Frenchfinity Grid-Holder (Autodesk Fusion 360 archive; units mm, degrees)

design "Grid-Holder" references "Base"
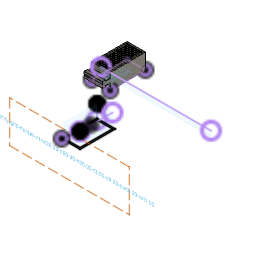
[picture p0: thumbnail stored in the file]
parameter "width" = 26
parameter "depth" = 50
parameter "height" = 20
parameter "outer_wall_thickness" = 2
parameter "inner_wall_thickness" = 1
sketch "Sketch1" plane through (0, 0, 0) normal (0, 0, 1) x axis (1, 0, 0)
  line L1 (26, 0) -> (0, 0)
  line L2 (0, 50) -> (0, 0)
  line L3 (26, 50) -> (0, 50)
  line L4 (26, 0) -> (26, 50)
  line L5 (24, 2) -> (2, 2)
  line L6 (24, 2) -> (24, 48)
  line L7 (24, 48) -> (2, 48)
  line L8 (2, 48) -> (2, 2)
  point P1 (0, 0)
  point P2 (0, 0)
  point P4 (0, 0)
  point P3 (26, 0)
  point P5 (0, 50)
  coincident P1 P2
  horizontal L1
  coincident P1 P4
  perpendicular L1 L2
  perpendicular L2 L3
  equal L1 L3
  dimension "d7" distance P2 P3 = 26 (= "width")
  dimension "d8" distance P4 P5 = 50 (= "depth")
  dimension "d11" = 2 (= "outer_wall_thickness")
extrude "Extrude1" new body sketch "Sketch1" against normal blind 2 (magnitude of "outer_wall_thickness * -1") bodies "Case"
extrude "Extrude2" add sketch "Sketch1" along normal blind 20 (= "height")
sketch "Sketch2" plane through (0, 0, 0) normal (0, 0, 1) x axis (1, 0, 0)
  line L1 (24, 48) -> (24, 2)
  line L2 (2, 48) -> (24, 48)
  line L3 (2, 2) -> (2, 48)
  line L4 (24, 2) -> (2, 2)
  line L5 (24, 25) -> (2, 25)
  line L6 (2, 25.5) -> (24, 25.5)
  line L7 (2, 24.5) -> (2, 25.5)
  line L8 (24, 24.5) -> (2, 24.5)
  line L9 (24, 25.5) -> (24, 24.5)
  line L10 (2, 24.5) -> (24, 25.5)
  line L11 (24, 24.5) -> (2, 25.5)
  point P6 (2, 25)
  point P7 (24, 25)
  point P12 (13, 25)
  point P9 (2, 25.5)
  point P10 (2, 24.5)
  point P11 (24, 24.5)
  midpoint L3 P6
  midpoint L1 P7
  horizontal L6
  perpendicular L6 L7
  parallel L6 L8
  parallel L7 L9
  coincident L10 P12
  coincident L11 P12
  midpoint L5 P12
  dimension "d16" distance P9 P10 = 1 (= "inner_wall_thickness")
  dimension "d23" distance P10 P11 = 22 (= "width - outer_wall_thickness - outer_wall_thickness")
extrude "Extrude3" new body sketch "Sketch2" profile of L1 L3 L6 L8 along normal blind 20 (= "height") bodies "Row-Divider"
sketch "Sketch3" plane through (0, 0, 0) normal (0, 0, 1) x axis (1, 0, 0)
  line L1 (24, 2) -> (2, 2)
  line L2 (24, 48) -> (2, 48)
  line L3 (13, 48) -> (13, 2)
  line L4 (13.5, 48) -> (12.5, 48)
  line L5 (13.5, 2) -> (13.5, 48)
  line L6 (12.5, 2) -> (13.5, 2)
  line L7 (12.5, 48) -> (12.5, 2)
  line L8 (13.5, 2) -> (12.5, 48)
  line L9 (12.5, 2) -> (13.5, 48)
  point P6 (13, 2)
  point P7 (13, 48)
  point P12 (13, 25)
  point P9 (13.5, 48)
  point P10 (13.5, 2)
  point P8 (12.5, 48)
  midpoint L1 P6
  midpoint L2 P7
  horizontal L4
  perpendicular L4 L5
  parallel L4 L6
  parallel L5 L7
  coincident L8 P12
  coincident L9 P12
  midpoint L3 P12
  dimension "d24" distance P9 P10 = 46 (= "depth - outer_wall_thickness - outer_wall_thickness")
  dimension "d25" distance P8 P9 = 1 (= "inner_wall_thickness")
extrude "Extrude4" new body sketch "Sketch3" profile of L4 L5 L6 L7 along normal blind 20 (= "height") bodies "Column-Divider"
sketch "Sketch5" plane through (0, 48, 0) normal (0, -1, 0) x axis (1, 0, 0)
  line L1 (24, 0) -> (2, 0)
  line L2 (24, 20) -> (24, 0)
  line L3 (2, 20) -> (24, 20)
  line L4 (2, 0) -> (2, 20)
  line L5 (2, 20) -> (2, 0)
  line L6 (4.4568, 20) -> (2, 20)
  point P7 (2, 20)
  point P8 (2, 20)
  point P9 (4.4568, 20)
  coincident P7 P8
  perpendicular L5 L6
  dimension "d32" distance P8 P9 = 2.4568 (= "column_width_calculated")
move "Move1"
rectangular_pattern "R-Pattern3" countU 8 (= "columns - 1") uSpaceDistance -2.4568 (= "column_width_calculated * -1") vSpaceDistance 0 bodies "Column-Divider (1)", "Column-Divider (2)", "Column-Divider (3)", "Column-Divider (4)", "Column-Divider (5)", "Column-Divider (6)", "Column-Divider (7)"
sketch "Sketch6" plane through (2, 0, 0) normal (1, 0, 0) x axis (0, 1, 0)
  line L1 (48, 0) -> (2, 0)
  line L2 (48, 20) -> (48, 0)
  line L3 (2, 20) -> (48, 20)
  line L4 (2, 0) -> (2, 20)
  line L5 (17.4444, 20) -> (2, 20)
  line L6 (2, 20) -> (48, 20)
  point P6 (2, 20)
  point P7 (2, 20)
  point P8 (17.4444, 20)
  coincident P6 P7
  parallel L5 L6
  dimension "d39" distance P7 P8 = 15.4444 (= "row_width_calculated")
move "Move2"
rectangular_pattern "R-Pattern4" countU 2 (= "rows - 1") uSpaceDistance 15.4444 (= "row_width_calculated") vSpaceDistance 0 bodies "Row-Divider (1)"
component_insert "Component Insert"
sketch "Sketch7" plane through (0, 55.6118, 0) normal (0, 1, 0) x axis (-1, 0, 0)
  line L1 (0, 52.6059) -> (-156, 52.6059)
  line L2 (0, 60) -> (0, 52.6059)
  line L3 (-156, 60) -> (0, 60)
  line L4 (-156, 52.6059) -> (-156, 60)
  line L5 (-156, 60) -> (0, 60)
combine "Combine1" bodies "Column-Divider (6)", "Column-Divider (3)", "Column-Divider (2)", "Row-Divider (1)", "Column-Divider (4)", "Column-Divider (5)", "Column-Divider (7)", "Column-Divider (1)"
move "Move3"
extrude "Extrude5" add of existing geometry to an object
extrude "Extrude6" add of existing geometry to an object
sketch "Text" plane through (0, 0, 38) normal (0, 0, -1) x axis (1, 0, 0)
  dimension "d48" = 3
extrude "Extrude7" cut sketch "Text" against normal blind 2
sketch "File name" plane through (0, 0, 0) normal (0, 1, 0) x axis (1, 0, 0)
  dimension "d51" = 5
named bodies: "Case", "Row-Divider", "Column-Divider", "Column-Divider (1)", "Column-Divider (2)", "Column-Divider (3)", "Column-Divider (4)", "Column-Divider (5)", "Column-Divider (6)", "Column-Divider (7)", "Row-Divider (1)"

design "Base"
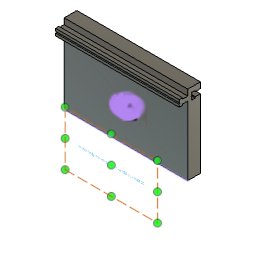
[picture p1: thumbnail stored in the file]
parameter "wall_anchor_height" = 60
parameter "wall_anchor_width" = 20
parameter "wall_anchor_angle" = 45
parameter "width_per_slot" = 40
parameter "slot_inner_width" = 8.5
parameter "slot_inner_height" = 4.5
parameter "slot_outer_width" = 5.6
parameter "slot_outer_height" = 6.5
parameter "slot_dept" = 15
parameter "print_tolerance" = 0.12
parameter "base_plate_thickness" = 16
parameter "base_plate_slot_height" = 50
parameter "wall_anchor_angle_rounded_border" = 1.5
parameter "base_plate_screw_hole_diameter" = 4
parameter "base_plate_screw_head_diameter" = 8
parameter "base_plate_screw_head_height" = 4
parameter "base_plate_screw_hole_side_distance" = 7
parameter "slot_screw_head_width" = 4.42 (= "4.3 mm + print_tolerance")
parameter "slot_screw_thread_width" = 2.12 (= "2 mm + print_tolerance")
parameter "slot_screw_head_height" = 2.12 (= "2 mm + print_tolerance")
parameter "width" = 156
parameter "filament_hole_width" = 1.7
parameter "plate_height" = 80
parameter "screw_plate_screw_head_widht" = 8
parameter "screw_plate_screw_head_height" = 4
parameter "screw_plate_screw_diameter" = 4
parameter "SkadisSlotW_1" = 5 comment "Skadis Slot Width"
parameter "SkadisSlotH_1" = 15 comment "Skadis Slot Height"
parameter "ClearanceHoriz_1" = 0.3 comment "Horizontal clearance for peg"
parameter "ClearanceVerticle_1" = 1 comment "Vertical clearance for peg"
parameter "PegW_1" = 4.7 (= "SkadisSlotW_1 - ClearanceHoriz_1") comment "Calculated Peg Width"
parameter "PegH_1" = 14 (= "SkadisSlotH_1 - ClearanceVerticle_1") comment "Calculated Peg Height"
parameter "PegD_1" = 5.2 (= "5 mm + 0.2 mm")
parameter "SkadisSlotW_2" = 5 comment "Skadis Slot Width"
parameter "SkadisSlotH_2" = 15 comment "Skadis Slot Height"
parameter "ClearanceHoriz_2" = 0.3 comment "Horizontal clearance for peg"
parameter "ClearanceVerticle_2" = 1 comment "Vertical clearance for peg"
parameter "PegW_2" = 4.7 (= "SkadisSlotW_2 - ClearanceHoriz_2") comment "Calculated Peg Width"
parameter "PegH_2" = 14 (= "SkadisSlotH_2 - ClearanceVerticle_2") comment "Calculated Peg Height"
parameter "PegD_2" = 5.2 (= "5 mm + 0.2 mm")
parameter "SkadisSlotW_3" = 5 comment "Skadis Slot Width"
parameter "SkadisSlotH_3" = 15 comment "Skadis Slot Height"
parameter "ClearanceHoriz_3" = 0.3 comment "Horizontal clearance for peg"
parameter "ClearanceVerticle_3" = 1 comment "Vertical clearance for peg"
parameter "PegW_3" = 4.7 (= "SkadisSlotW_3 - ClearanceHoriz_3") comment "Calculated Peg Width"
parameter "PegH_3" = 14 (= "SkadisSlotH_3 - ClearanceVerticle_3") comment "Calculated Peg Height"
parameter "PegD_3" = 5.2 (= "5 mm + 0.2 mm")
sketch "Side" plane through (0, 0, 0) normal (1, 0, 0) x axis (0, 1, 0)
  line L1 (39.6118, 0) -> (19.6118, 0)
  line L2 (39.6118, 60) -> (39.6118, 0)
  line L3 (19.6118, 60) -> (39.6118, 60)
  line L4 (19.6118, 0) -> (19.6118, 60)
  line L5 (39.6118, 39.6118) -> (0, 0)
  line L6 (56.0196, 0) -> (0, 0)
  point P1 (0, 0)
  point P6 (0, 0)
  point P7 (39.6118, 39.6118)
  point P2 (19.6118, 0)
  point P3 (39.6118, 0)
  point P5 (19.6118, 60)
  horizontal L1
  vertical L2
  horizontal L3
  vertical L4
  horizontal L6
  coincident P1 P6
  coincident L2 P7
  dimension "d4" distance P2 P3 = 20 (= "wall_anchor_width")
  dimension "d5" distance P2 P5 = 60 (= "wall_anchor_height")
  dimension "d6" angle L5 L6 = 45 (= "wall_anchor_angle")
extrude "Extrude1" new body sketch "Side" profile of L1 L2 L3 L4 L5 along normal blind 40 (= "width_per_slot")
sketch "Slot LeftToRight" plane through (0, 0, 0) normal (-1, 0, 0) x axis (0, -1, 0)
  line L1 (-19.6118, 60) -> (-19.6118, 19.6118)
  line L2 (-39.6118, 60) -> (-19.6118, 60)
  line L3 (-39.6118, 39.6118) -> (-39.6118, 60)
  line L4 (-19.6118, 19.6118) -> (-39.6118, 39.6118)
  line L5 (-39.6118, 52.6059) -> (-39.6118, 49.8059)
  line L6 (-39.6118, 47.0059) -> (-39.6118, 49.8059)
  line L7 (-33.1118, 52.6059) -> (-39.6118, 52.6059)
  line L8 (-28.6118, 49.8059) -> (-39.6118, 49.8059)
  line L9 (-28.6118, 54.0559) -> (-28.6118, 49.8059)
  line L10 (-33.1118, 54.0559) -> (-28.6118, 54.0559)
  line L11 (-33.1118, 52.6059) -> (-33.1118, 54.0559)
  line L12 (-28.6118, 45.5559) -> (-28.6118, 49.8059)
  line L13 (-33.1118, 45.5559) -> (-28.6118, 45.5559)
  line L14 (-33.1118, 47.0059) -> (-33.1118, 45.5559)
  line L15 (-33.1118, 47.0059) -> (-39.6118, 47.0059)
  point P6 (-39.6118, 49.8059)
  point P7 (-39.6118, 52.6059)
  point P17 (-39.6118, 47.0059)
  point P9 (-33.1118, 52.6059)
  point P16 (-33.1118, 47.0059)
  point P10 (-28.6118, 49.8059)
  point P13 (-28.6118, 49.8059)
  point P11 (-28.6118, 54.0559)
  point P14 (-28.6118, 45.5559)
  point P12 (-33.1118, 54.0559)
  point P15 (-33.1118, 45.5559)
  midpoint L3 P6
  parallel L3 L5
  parallel L3 L6
  perpendicular L3 L7
  perpendicular L6 L8
  perpendicular L8 L9
  perpendicular L9 L10
  symmetric P7 L8 P17
  symmetric P9 L8 P16
  symmetric P10 L8 P13
  symmetric L8 P11 P14
  symmetric L8 P12 P15
  dimension "d80" distance P6 P7 = 2.8 (= "slot_outer_width / 2")
  dimension "d82" distance P7 P9 = 6.5 (= "slot_outer_height")
  dimension "d84" distance P6 P10 = 11 (= "slot_outer_height + slot_inner_height")
  dimension "d85" distance P10 P11 = 4.25 (= "slot_inner_width / 2")
  dimension "d86" distance P11 P12 = 4.5 (= "slot_inner_height")
extrude "Extrude3" cut sketch "Slot LeftToRight" profile of L3 L5 L6 L7 L9 L10 L11 L12 L13 L14 L15 against normal blind 40 (magnitude of "width_per_slot * -1")
sketch "Plate" plane through (0, 39.6118, 0) normal (0, 1, 0) x axis (-1, 0, 0)
  line L1 (0, 39.6118) -> (-40, 39.6118)
  line L2 (-40, 60) -> (0, 60)
  line L3 (0, 10) -> (0, 60)
  line L4 (-40, 10) -> (-40, 60)
  line L5 (-40, 10) -> (0, 10)
  line L6 (-40, 47.0059) -> (0, 47.0059)
  line L7 (-40, 52.6059) -> (-40, 60)
  line L8 (0, 60) -> (0, 52.6059)
  line L9 (0, 52.6059) -> (-40, 52.6059)
  line L10 (-40, 60) -> (0, 60)
  line L11 (-40, 39.6118) -> (-40, 47.0059)
  line L12 (0, 47.0059) -> (0, 39.6118)
  point P2 (0, 60)
  point P3 (-40, 60)
  point P4 (0, 10)
  point P5 (-40, 10)
  perpendicular L1 L3
  perpendicular L1 L4
  dimension "d36" distance P2 P3 = 40 (= "width_per_slot")
  dimension "d37" distance P2 P4 = 50 (= "base_plate_slot_height")
  dimension "d39" distance P3 P5 = 50 (= "base_plate_slot_height")
extrude "Extrude6" new body sketch "Plate" profile of L1 L2 L3 L4 L5 L6 L7 L8 L9 L10 along normal blind 16 (= "base_plate_thickness") bodies "Base plate with slot"
sketch "Slot" plane through (0, 0, 0) normal (-1, 0, 0) x axis (0, -1, 0)
  line L1 (-19.6118, 60) -> (-19.6118, 19.6118)
  line L2 (-39.6118, 60) -> (-19.6118, 60)
  line L3 (-39.6118, 52.6059) -> (-39.6118, 60)
  line L4 (-33.1118, 52.6059) -> (-39.6118, 52.6059)
  line L5 (-33.1118, 54.0559) -> (-33.1118, 52.6059)
  line L6 (-28.6118, 54.0559) -> (-33.1118, 54.0559)
  line L7 (-28.6118, 45.5559) -> (-28.6118, 54.0559)
  line L8 (-33.1118, 45.5559) -> (-28.6118, 45.5559)
  line L9 (-33.1118, 47.0059) -> (-33.1118, 45.5559)
  line L10 (-39.6118, 47.0059) -> (-33.1118, 47.0059)
  line L11 (-39.6118, 39.6118) -> (-39.6118, 47.0059)
  line L12 (-19.6118, 19.6118) -> (-39.6118, 39.6118)
  line L13 (-33.1118, 52.6059) -> (-39.6118, 52.6059)
  line L14 (-33.1118, 54.0559) -> (-33.1118, 52.6059)
  line L15 (-28.6118, 54.0559) -> (-33.1118, 54.0559)
  line L16 (-28.6118, 45.5559) -> (-28.6118, 54.0559)
  line L17 (-33.1118, 45.5559) -> (-28.6118, 45.5559)
  line L18 (-33.1118, 47.0059) -> (-33.1118, 45.5559)
  line L19 (-39.6118, 47.0059) -> (-33.1118, 47.0059)
  line L20 (-39.6118, 10) -> (-39.6118, 60)
  line L21 (-32.9918, 52.4859) -> (-39.6118, 52.4859)
  line L22 (-32.9918, 53.9359) -> (-32.9918, 52.4859)
  line L23 (-28.7318, 53.9359) -> (-32.9918, 53.9359)
  line L24 (-28.7318, 45.6759) -> (-28.7318, 53.9359)
  line L25 (-32.9918, 45.6759) -> (-28.7318, 45.6759)
  line L26 (-32.9918, 47.1259) -> (-32.9918, 45.6759)
  line L27 (-39.6118, 47.1259) -> (-32.9918, 47.1259)
  line L28 (-33.1118, 52.6059) -> (-39.6118, 52.6059)
  line L29 (-33.1118, 52.6059) -> (-33.1118, 54.0559)
  line L30 (-28.6118, 54.0559) -> (-33.1118, 54.0559)
  line L31 (-28.6118, 45.5559) -> (-28.6118, 54.0559)
  line L32 (-33.1118, 45.5559) -> (-28.6118, 45.5559)
  line L33 (-33.1118, 47.0059) -> (-33.1118, 45.5559)
  line L34 (-39.6118, 47.0059) -> (-33.1118, 47.0059)
  line L35 (-39.6118, 47.0059) -> (-39.6118, 52.6059)
  line L36 (-49.1118, 52.6059) -> (-55.6118, 52.6059)
  line L37 (-49.1118, 52.6059) -> (-49.1118, 54.0559)
  line L38 (-44.6118, 54.0559) -> (-49.1118, 54.0559)
  line L39 (-44.6118, 45.5559) -> (-44.6118, 54.0559)
  line L40 (-49.1118, 45.5559) -> (-44.6118, 45.5559)
  line L41 (-49.1118, 47.0059) -> (-49.1118, 45.5559)
  line L42 (-55.6118, 47.0059) -> (-49.1118, 47.0059)
  line L43 (-55.6118, 47.0059) -> (-55.6118, 52.6059)
  point P15 (-39.6118, 52.6059)
  point P33 (-39.6118, 52.6059)
  point P16 (-33.1118, 52.6059)
  point P34 (-33.1118, 52.6059)
  point P17 (-33.1118, 54.0559)
  point P35 (-33.1118, 54.0559)
  point P36 (-33.1118, 52.6059)
  point P18 (-28.6118, 54.0559)
  point P37 (-28.6118, 54.0559)
  point P19 (-28.6118, 45.5559)
  point P38 (-28.6118, 45.5559)
  point P10 (-28.6118, 45.5559)
  point P39 (-28.6118, 45.5559)
  point P11 (-33.1118, 45.5559)
  point P40 (-33.1118, 45.5559)
  point P41 (-33.1118, 45.5559)
  point P12 (-33.1118, 47.0059)
  point P42 (-33.1118, 47.0059)
  point P21 (-33.1118, 47.0059)
  point P43 (-33.1118, 47.0059)
  point P22 (-39.6118, 47.0059)
  point P44 (-39.6118, 47.0059)
  point P45 (-39.6118, 52.6059)
  point P46 (-39.6118, 47.0059)
  coincident P15 P33
  coincident P16 P34
  coincident P17 P35
  coincident P16 P36
  coincident P18 P37
  coincident P19 P38
  coincident P10 P39
  coincident P11 P40
  coincident P11 P41
  coincident P12 P42
  coincident P21 P43
  coincident P22 P44
  coincident P15 P45
  coincident P22 P46
  dimension "d91" = 0.12 (= "print_tolerance")
  dimension "d96" R-Pattern1-uDistance = -16 (= "base_plate_thickness * -1")
  dimension "d97" R-Pattern1-vDistance = 0
extrude "Extrude7" add sketch "Slot" profile of L20 L24 L23 L27 L22 L25 L26 L21 against normal blind 40 (magnitude of "width_per_slot * -1")
extrude "Extrude8" cut sketch "Slot" profile of L36 L37 L38 L39 L40 L41 L42 L43 no distance stored
sketch "Sketch3" plane through (0, 0, 0) normal (-1, 0, 0) x axis (0, -1, 0)
  line L1 (-32.9918, 47.1259) -> (-39.6118, 47.1259)
  line L2 (-32.9918, 45.6759) -> (-32.9918, 47.1259)
  line L3 (-28.7318, 45.6759) -> (-32.9918, 45.6759)
  line L4 (-28.7318, 53.9359) -> (-28.7318, 45.6759)
  line L5 (-32.9918, 53.9359) -> (-28.7318, 53.9359)
  line L6 (-32.9918, 52.4859) -> (-32.9918, 53.9359)
  line L7 (-39.6118, 52.4859) -> (-32.9918, 52.4859)
  line L8 (-44.6118, 45.5559) -> (-44.6118, 54.0559)
  line L9 (-32.9918, 52.4859) -> (-39.6118, 52.4859)
  line L10 (-32.9918, 53.9359) -> (-32.9918, 52.4859)
  line L11 (-28.7318, 53.9359) -> (-32.9918, 53.9359)
  line L12 (-28.7318, 45.6759) -> (-28.7318, 53.9359)
  line L13 (-32.9918, 45.6759) -> (-28.7318, 45.6759)
  line L14 (-32.9918, 47.1259) -> (-32.9918, 45.6759)
  line L15 (-39.6118, 47.1259) -> (-32.9918, 47.1259)
  line L16 (-39.6118, 47.1259) -> (-39.6118, 52.4859)
  line L17 (-55.6118, 52.4859) -> (-48.9918, 52.4859)
  line L18 (-48.9918, 52.4859) -> (-48.9918, 53.9359)
  line L19 (-48.9918, 53.9359) -> (-44.7318, 53.9359)
  line L20 (-44.7318, 45.6759) -> (-44.7318, 53.9359)
  line L21 (-48.9918, 45.6759) -> (-44.7318, 45.6759)
  line L22 (-48.9918, 47.1259) -> (-48.9918, 45.6759)
  line L23 (-55.6118, 47.1259) -> (-48.9918, 47.1259)
  line L24 (-55.6118, 47.1259) -> (-55.6118, 52.4859)
  line L25 (-55.6118, 47.0059) -> (-49.1118, 47.0059)
  line L26 (-55.6118, 10) -> (-55.6118, 47.0059)
  line L27 (-39.6118, 10) -> (-55.6118, 10)
  line L28 (-39.6118, 47.1259) -> (-39.6118, 10)
  line L29 (-39.6118, 60) -> (-39.6118, 52.4859)
  line L30 (-55.6118, 60) -> (-39.6118, 60)
  line L31 (-55.6118, 52.6059) -> (-55.6118, 60)
  line L32 (-49.1118, 52.6059) -> (-55.6118, 52.6059)
  line L33 (-49.1118, 54.0559) -> (-49.1118, 52.6059)
  line L34 (-44.6118, 54.0559) -> (-49.1118, 54.0559)
  line L35 (-49.1118, 45.5559) -> (-44.6118, 45.5559)
  line L36 (-49.1118, 47.0059) -> (-49.1118, 45.5559)
  point P9 (-39.6118, 52.4859)
  point P20 (-39.6118, 52.4859)
  point P19 (-39.6118, 47.1259)
  point P21 (-39.6118, 47.1259)
  coincident P9 P20
  coincident P19 P21
  dimension "d105" R-Pattern1-vDistance = 0
extrude "Extrude3" new body sketch "Sketch3" profile of L17 L18 L19 L20 L21 L22 L23 L24 against normal blind 40 (magnitude of "width_per_slot * -1")
sketch "Screw hole" plane through (0, 28.6118, 0) normal (0, 1, 0) x axis (-1, 0, 0)
  line L1 (0, 54.0559) -> (0, 45.5559)
  line L2 (-40, 54.0559) -> (0, 54.0559)
  line L3 (-40, 45.5559) -> (-40, 54.0559)
  line L4 (0, 45.5559) -> (-40, 45.5559)
  line L5 (0, 45.5559) -> (-40, 54.0559)
  line L6 (-40, 45.5559) -> (0, 54.0559)
  circle C1 centre (-20, 49.8059) radius 2.21
  circle C2 centre (-20, 49.8059) radius 1.06
  point P4 (-40, 54.0559)
  point P6 (-40, 54.0559)
  point P2 (0, 45.5559)
  point P7 (0, 45.5559)
  point P3 (0, 54.0559)
  point P8 (0, 54.0559)
  point P5 (-40, 45.5559)
  point P9 (-40, 45.5559)
  point P10 (-20, 49.8059)
  coincident P4 P6
  coincident P2 P7
  coincident P3 P8
  coincident P5 P9
  midpoint L5 P10
  concentric C1 C2
  dimension "d119" diameter C1 = 4.42 (= "slot_screw_head_width")
  dimension "d120" diameter C2 = 2.12 (= "slot_screw_thread_width")
extrude "Extrude4" cut sketch "Screw hole" profile of C2 against normal blind 2000
extrude "Extrude5" cut sketch "Screw hole" profile of C1 C2 no distance stored
fillet "Fillet1" radius 1.5 (= "wall_anchor_angle_rounded_border")
work_plane "WorkPlane1" sketch "Slot LeftToRight" AlongDistance -20 (= "-width_per_slot / 2")
sketch "Screw head" plane through (20, 0, 0) normal (-1, 0, 0) x axis (0, -1, 0)
  line L1 (-28.6118, 52.0159) -> (-28.6118, 47.5959)
  line L2 (-26.4918, 52.0159) -> (-26.4918, 47.5959)
  line L3 (-26.4918, 48.7459) -> (-26.4918, 50.8659)
  line L4 (-26.4918, 50.8659) -> (-28.6118, 52.0159)
  line L5 (-26.4918, 52.0159) -> (-28.6118, 52.0159)
  point P3 (-28.6118, 52.0159)
  point P8 (-28.6118, 52.0159)
  point P6 (-26.4918, 50.8659)
  point P9 (-26.4918, 50.8659)
  point P10 (-28.6118, 52.0159)
  point P5 (-26.4918, 52.0159)
  point P11 (-26.4918, 52.0159)
  coincident P3 P8
  coincident P6 P9
  coincident P3 P10
  coincident P5 P11
revolve "Revolve1" sketch "Screw head" AlongAngle 360
rectangular_pattern "R-Pattern2" countU 3 (= "floor(( width / mm ) / ( width_per_slot / cm * 10 ))") uSpaceDistance 40 (= "width_per_slot") vSpaceDistance 0 bodies "Wall anchor part (1)", "Wall anchor part (2)"
work_plane "WorkPlane2"
extrude "Extrude12" new body of existing geometry no distance stored
mirror "Mirror3" mirrorStitchTolerance 0.1
sketch "filename" plane through (0, 19.6118, 0) normal (0, -1, 0) x axis (1, 0, 0)
  dimension "d216" = 3
sketch "Text" plane through (0, 19.6118, 0) normal (0, -1, 0) x axis (1, 0, 0)
  line L1 (138, 60) -> (138, 23.2332)
  line L2 (120, 23.2332) -> (120, 60)
  line L3 (138, 23.2332) -> (120, 23.2332)
  line L4 (138, 60) -> (138, 23.2332)
  line L5 (120, 60) -> (138, 60)
  line L6 (0, 60) -> (0, 23.2332)
  line L7 (-18, 60) -> (0, 60)
  line L8 (-18, 23.2332) -> (-18, 60)
  line L9 (0, 23.2332) -> (-18, 23.2332)
  curve K1
  curve K2
  curve K3
  curve K4
  line L10 (80, 60) -> (40, 60)
  point P4 (138, 23.2332)
  point P2 (-18, 60)
  coincident P4
  coincident P2
  parallel K3 L10
  dimension "d229" Text1-Height = 3
extrude "Extrude19" cut sketch "Text" against normal blind 2
extrude "Extrude14" cut of existing geometry blind 58 (= "( width_per_slot - width ) / -2")
extrude "Extrude15" cut of existing geometry blind 58 (= "( width_per_slot - width ) / -2")
extrude "Extrude9" cut of existing geometry blind -39 (= "-width_per_slot + 1 mm")
extrude "Extrude10" add of existing geometry blind 155 (= "width - 1 mm")
extrude "Extrude13" cut of existing geometry blind -30
extrude "Extrude14" add of existing geometry blind 80 (= "plate_height")
sketch "Sketch7" plane through (0, 39.6118, 0) normal (0, -1, 0) x axis (1, 0, 0)
  dimension "d236" = 3
extrude "Extrude11" cut sketch "Sketch7" against normal blind 2
sketch "File name" plane through (0, 39.6118, 0) normal (0, -1, 0) x axis (1, 0, 0)
  line L1 (0, 47.1259) -> (156, 47.1259)
  line L2 (0, -40) -> (0, 47.1259)
  line L3 (156, 47.1259) -> (156, -40)
  curve K1
  curve K2
  curve K3
  curve K4
  line L4 (156, -40) -> (0, -40)
  curve K5 (72.5535, 1.3958) -> (72.2323, 1.801)
  curve K6 (72.662, 0.8249) -> (72.5535, 1.3958)
  curve K7 (72.5413, 0.2233) -> (72.662, 0.8249)
  curve K8 (77.3073, 0.5793) -> (77.162, 1.0582)
  curve K9 (77.0351, -0.0673) -> (77.3073, 0.5793)
  curve K10 (75.6866, 2.5111) -> (75.4512, 1.9606)
  curve K11 (76.3128, 2.7342) -> (75.6866, 2.5111)
  curve K12 (76.9451, 2.505) -> (76.3128, 2.7342)
  curve K13 (77.1845, 1.9504) -> (76.9451, 2.505)
  curve K14 (77.074, 1.5862) -> (77.1845, 1.9504)
  curve K15 (76.7425, 1.3488) -> (77.074, 1.5862)
  curve K16 (77.162, 1.0582) -> (76.7425, 1.3488)
  line L5 (83.8813, 4.404) -> (83.8813, 4.8235)
  line L6 (83.4618, 4.404) -> (83.8813, 4.404)
  curve K17 (84.4696, 2.7342) -> (83.9253, 2.5582)
  curve K18 (84.8932, 2.6359) -> (84.4696, 2.7342)
  curve K19 (85.1941, 2.3556) -> (84.8932, 2.6359)
  curve K20 (85.3803, 1.9095) -> (85.1941, 2.3556)
  curve K21 (85.4478, 1.2014) -> (85.3803, 1.9095)
  curve K22 (85.3394, 0.3481) -> (85.4478, 1.2014)
  curve K23 (85.014, -0.1533) -> (85.3394, 0.3481)
  curve K24 (84.4696, -0.3293) -> (85.014, -0.1533)
  curve K25 (83.7882, -0.0182) -> (84.4696, -0.3293)
  curve K26 (83.4915, 1.2014) -> (83.7882, -0.0182)
  line L7 (71.1108, 1.6128) -> (71.1108, 1.8952)
  curve K27 (72.2323, 1.801) -> (71.7411, 1.9443)
  curve K28 (76.3189, -0.3293) -> (77.0351, -0.0673)
  curve K29 (75.6027, -0.0673) -> (76.3189, -0.3293)
  curve K30 (75.3305, 0.5896) -> (75.6027, -0.0673)
  curve K31 (75.4778, 1.0786) -> (75.3305, 0.5896)
  curve K32 (75.9014, 1.3488) -> (75.4778, 1.0786)
  line L8 (80.6224, -0.2781) -> (80.6224, 0.1414)
  line L9 (80.2029, -0.2781) -> (80.6224, -0.2781)
  curve K33 (82.1388, 2.7342) -> (81.5945, 2.5582)
  curve K34 (82.5624, 2.6359) -> (82.1388, 2.7342)
  curve K35 (82.8632, 2.3556) -> (82.5624, 2.6359)
  curve K36 (83.0495, 1.9095) -> (82.8632, 2.3556)
  curve K37 (78.6436, 2.7342) -> (78.0993, 2.5582)
  curve K38 (79.0672, 2.6359) -> (78.6436, 2.7342)
  curve K39 (79.368, 2.3556) -> (79.0672, 2.6359)
  curve K40 (79.5542, 1.9095) -> (79.368, 2.3556)
  curve K41 (87.7285, 7.4163) -> (87.1842, 7.2403)
  curve K42 (88.1521, 7.3181) -> (87.7285, 7.4163)
  curve K43 (88.4529, 7.0377) -> (88.1521, 7.3181)
  curve K44 (88.6392, 6.5916) -> (88.4529, 7.0377)
  curve K45 (85.3977, 7.4163) -> (84.8533, 7.2403)
  curve K46 (85.8213, 7.3181) -> (85.3977, 7.4163)
  curve K47 (86.1221, 7.0377) -> (85.8213, 7.3181)
  curve K48 (86.3083, 6.5916) -> (86.1221, 7.0377)
  line L10 (80.4413, 7.3631) -> (78.9495, 7.3631)
  line L11 (80.4413, 7.0111) -> (80.4413, 7.3631)
  line L12 (79.2442, 7.0111) -> (80.4413, 7.0111)
  curve K49 (83.5999, 2.0568) -> (83.4915, 1.2014)
  curve K50 (83.9253, 2.5582) -> (83.5999, 2.0568)
  curve K51 (86.8588, 6.7389) -> (86.7503, 5.8836)
  curve K52 (87.1842, 7.2403) -> (86.8588, 6.7389)
  curve K53 (77.7739, 2.0568) -> (77.6654, 1.2014)
  curve K54 (78.0993, 2.5582) -> (77.7739, 2.0568)
  curve K55 (81.2691, 2.0568) -> (81.1606, 1.2014)
  curve K56 (81.5945, 2.5582) -> (81.2691, 2.0568)
  line L13 (71.1108, 1.8952) -> (70.7752, 1.8952)
  curve K57 (71.3789, 1.8604) -> (71.1108, 1.6128)
  curve K58 (71.7411, 1.9443) -> (71.3789, 1.8604)
  curve K59 (84.528, 6.7389) -> (84.4195, 5.8836)
  curve K60 (84.8533, 7.2403) -> (84.528, 6.7389)
  dimension "d239" Text1-Height = 3
sketch "Sketch4" plane through (40, 0, 0) normal (1, 0, 0) x axis (0, 1, 0)
  line L1 (44.7318, 53.9359) -> (48.9918, 53.9359)
  line L2 (44.7318, 45.6759) -> (44.7318, 53.9359)
  line L3 (48.9918, 45.6759) -> (44.7318, 45.6759)
  line L4 (48.9918, 47.1259) -> (48.9918, 45.6759)
  line L5 (55.6118, 47.1259) -> (48.9918, 47.1259)
  line L6 (55.6118, 52.4859) -> (55.6118, 47.1259)
  line L7 (48.9918, 52.4859) -> (55.6118, 52.4859)
  line L8 (48.9918, 53.9359) -> (48.9918, 52.4859)
  circle C1 centre (44.7318, 49.8059) radius 0.85
  point P10 (44.7318, 49.8059)
  midpoint L2 P10
  dimension "d241" diameter C1 = 1.7 (= "filament_hole_width")
extrude "Extrude4" cut sketch "Sketch4" profile of L2 C1 no distance stored
sketch "Sketch15" plane through (-18, 0, 0) normal (-1, 0, 0) x axis (0, -1, 0)
  line L1 (-19.6118, 60) -> (-19.6118, 23.2332)
  line L2 (-39.6118, 60) -> (-19.6118, 60)
  line L3 (-39.6118, 52.6059) -> (-39.6118, 60)
  line L4 (-33.1118, 52.6059) -> (-39.6118, 52.6059)
  line L5 (-33.1118, 54.0559) -> (-33.1118, 52.6059)
  line L6 (-28.6118, 54.0559) -> (-33.1118, 54.0559)
  line L7 (-28.6118, 45.5559) -> (-28.6118, 54.0559)
  line L8 (-33.1118, 45.5559) -> (-28.6118, 45.5559)
  line L9 (-33.1118, 47.0059) -> (-33.1118, 45.5559)
  line L10 (-39.6118, 47.0059) -> (-33.1118, 47.0059)
  line L11 (-39.6118, 39.6118) -> (-39.6118, 47.0059)
  line L12 (-22.1725, 22.1725) -> (-39.6118, 39.6118)
  arc A1 centre (-21.1118, 23.2332) radius 1.5 clockwise from (-19.6118, 23.2332) to (-22.1725, 22.1725)
  circle C1 centre (-28.6118, 49.8059) radius 0.85
  point P16 (-28.6118, 49.8059)
  midpoint L7 P16
  dimension "d244" diameter C1 = 1.7 (= "filament_hole_width")
sketch "Sketch9" plane through (156, 0, 0) normal (1, 0, 0) x axis (0, 1, 0)
  line L1 (49.1118, 47.0059) -> (55.6118, 47.0059)
  line L2 (49.1118, 45.5559) -> (49.1118, 47.0059)
  line L3 (44.6118, 45.5559) -> (49.1118, 45.5559)
  line L4 (44.6118, 54.0559) -> (44.6118, 45.5559)
  line L5 (49.1118, 54.0559) -> (44.6118, 54.0559)
  line L6 (49.1118, 52.6059) -> (49.1118, 54.0559)
  line L7 (55.6118, 52.6059) -> (49.1118, 52.6059)
  line L8 (55.6118, 47.0059) -> (55.6118, -40)
  line L9 (39.6118, 60) -> (55.6118, 60)
  line L10 (39.6118, 52.4859) -> (39.6118, 60)
  line L11 (32.9918, 52.4859) -> (39.6118, 52.4859)
  line L12 (32.9918, 53.9359) -> (32.9918, 52.4859)
  line L13 (28.7318, 53.9359) -> (32.9918, 53.9359)
  line L14 (28.7318, 45.6759) -> (28.7318, 53.9359)
  line L15 (32.9918, 45.6759) -> (28.7318, 45.6759)
  line L16 (32.9918, 47.1259) -> (32.9918, 45.6759)
  line L17 (39.6118, 47.1259) -> (32.9918, 47.1259)
  line L18 (55.6118, 60) -> (55.6118, 52.6059)
  line L19 (39.6118, -40) -> (39.6118, 47.1259)
  line L20 (55.6118, -40) -> (39.6118, -40)
  circle C1 centre (28.7318, 49.8059) radius 0.85
  circle C2 centre (44.6118, 49.8059) radius 0.85
  point P20 (28.7318, 49.8059)
  point P21 (44.6118, 49.8059)
  midpoint L14 P20
  midpoint L4 P21
  dimension "d247" diameter C1 = 1.7 (= "filament_hole_width")
  dimension "d250" diameter C2 = 1.7 (= "filament_hole_width")
extrude "Extrude12" cut sketch "Sketch9" profile of L4 L14 C1 C2 no distance stored
sketch "Sketch16" plane through (0, 19.6118, 0) normal (0, -1, 0) x axis (1, 0, 0)
  dimension "d253" = 3
extrude "Extrude22" cut sketch "Sketch16" against normal blind 2
extrude "Extrude23" cut sketch "Sketch15" profile of L7 C1 against normal blind 260 and along normal blind 80
sketch "Sketch17" plane through (0, 19.6118, 0) normal (0, -1, 0) x axis (1, 0, 0)
  dimension "d258" = 3
extrude "Extrude24" cut sketch "Sketch17" against normal blind 2
extrude "Extrude26" cut sketch "Text" against normal blind 2
extrude "Extrude27" cut sketch "Text" against normal blind 2
sketch "Sketch1" plane through (156, 0, 0) normal (1, 0, 0) x axis (0, 1, 0)
  line L1 (28.7318, 45.6759) -> (28.7318, 48.9559)
  line L2 (32.9918, 45.6759) -> (28.7318, 45.6759)
  line L3 (32.9918, 47.1259) -> (32.9918, 45.6759)
  line L4 (39.6118, 47.1259) -> (32.9918, 47.1259)
  line L5 (39.6118, -40) -> (39.6118, 47.1259)
  line L6 (55.6118, -40) -> (39.6118, -40)
  line L7 (55.6118, 47.0059) -> (55.6118, -40)
  line L8 (49.1118, 47.0059) -> (55.6118, 47.0059)
  line L9 (49.1118, 45.5559) -> (49.1118, 47.0059)
  line L10 (44.6118, 45.5559) -> (49.1118, 45.5559)
  line L11 (44.6118, 48.9559) -> (44.6118, 45.5559)
  line L12 (44.6118, 54.0559) -> (44.6118, 50.6559)
  line L13 (49.1118, 54.0559) -> (44.6118, 54.0559)
  line L14 (49.1118, 52.6059) -> (49.1118, 54.0559)
  line L15 (55.6118, 52.6059) -> (49.1118, 52.6059)
  line L16 (55.6118, 60) -> (55.6118, 52.6059)
  line L17 (39.6118, 60) -> (55.6118, 60)
  line L18 (39.6118, 52.4859) -> (39.6118, 60)
  line L19 (32.9918, 52.4859) -> (39.6118, 52.4859)
  line L20 (32.9918, 53.9359) -> (32.9918, 52.4859)
  line L21 (28.7318, 53.9359) -> (32.9918, 53.9359)
  line L22 (28.7318, 50.6559) -> (28.7318, 53.9359)
  line L23 (55.6118, 47.0059) -> (55.6118, -40)
  line L24 (39.6118, 47.1259) -> (39.6118, 52.4859)
  arc A1 centre (28.7318, 49.8059) radius 0.85 clockwise from (28.7318, 50.6559) to (28.7318, 48.9559)
  arc A2 centre (44.6118, 49.8059) radius 0.85 clockwise from (44.6118, 48.9559) to (44.6118, 50.6559)
  point P24 (39.6118, 52.4859)
  point P30 (39.6118, 52.4859)
  point P8 (39.6118, 47.1259)
  point P31 (39.6118, 47.1259)
  coincident P24 P30
  coincident P8 P31
extrude "Extrude1" new body sketch "Sketch1" profile of L5 L6 L7 L8 L9 L10 L11 A2 L12 L13 L14 L15 L16 L17 L18 L23 L24 along normal blind 156 (= "width") bodies "Screw plate"
sketch "Screw Base" plane through (0, 55.6118, 0) normal (0, 1, 0) x axis (-1, 0, 0)
  line L1 (-156, 47.0059) -> (-156, -40)
  line L2 (-312, 47.0059) -> (-156, 47.0059)
  line L3 (-312, -40) -> (-312, 47.0059)
  line L4 (-156, -40) -> (-312, -40)
  line L5 (-234, -40) -> (-234, 47.0059)
  line L6 (-234, 35.0059) -> (-234, 47.0059)
  circle C1 centre (-234, 35.0059) radius 4
  circle C2 centre (-234, 35.0059) radius 2
  point P6 (-234, 47.0059)
  point P7 (-234, -40)
  point P8 (-234, 35.0059)
  point P9 (-234, 35.0059)
  midpoint L2 P6
  midpoint L4 P7
  perpendicular L2 L6
  coincident P8 P9
  concentric C1 C2
  dimension "d276" distance P6 P8 = 12
  dimension "d280" diameter C1 = 8 (= "screw_plate_screw_head_widht")
  dimension "d281" diameter C2 = 4 (= "base_plate_screw_hole_diameter")
work_plane "WorkPlane1" sketch "Screw Base" AlongDistance -4 (= "screw_plate_screw_head_height * -1")
sketch "Screw Head" plane through (0, 51.6118, 0) normal (0, 1, 0) x axis (1, 0, 0)
  circle C1 centre (234, -35.0059) radius 2
extrude "Extrude2" new body sketch "Screw Head" to an object bodies "Screw hole"
loft "Loft1" sketch "Screw Head" + "Screw Base"
rectangular_pattern "R-Pattern1" countU 5 (= "floor(width / 30 / mm)") uSpaceDistance 30 vSpaceDistance 62 (= "plate_height - 18 mm") bodies "Screw hole (5)", "Screw hole (6)", "Screw hole (3)", "Screw hole (1)", "Screw hole (7)", "Screw hole (8)", "Screw hole (9)", "Screw hole (2)"
split "Split1" bodies "Screw plate (4)", "Screw plate (5)", "Screw plate (1)", "Screw plate (3)", "Screw plate (2)", "Screw plate"
sketch "Text" plane through (0, 39.6118, 0) normal (0, -1, 0) x axis (1, 0, 0)
  dimension "d289" = 3
sketch "Filename" plane through (0, 0, 0) normal (0, 1, 0) x axis (1, 0, 0)
  dimension "d290" = 5
extrude "Extrude3" cut sketch "Text" against normal blind 2
sketch "Sketch6" plane through (0, 0, 0) normal (0, 1, 0) x axis (1, 0, 0)
  dimension "d293" = 5
sketch "Sketch1" plane through (204, 0, 0) normal (1, 0, 0) x axis (0, 1, 0)
  line L1 (44.6118, 54.0559) -> (44.6118, 50.6559)
  line L2 (49.1118, 54.0559) -> (44.6118, 54.0559)
  line L3 (49.1118, 52.6059) -> (49.1118, 54.0559)
  line L4 (55.6118, 52.6059) -> (49.1118, 52.6059)
  line L5 (55.6118, 60) -> (55.6118, 52.6059)
  line L6 (39.6118, 60) -> (55.6118, 60)
  line L7 (39.6118, -40) -> (39.6118, 60)
  line L8 (55.6118, -40) -> (39.6118, -40)
  line L9 (55.6118, 47.0059) -> (55.6118, -40)
  line L10 (49.1118, 47.0059) -> (55.6118, 47.0059)
  line L11 (49.1118, 45.5559) -> (49.1118, 47.0059)
  line L12 (44.6118, 45.5559) -> (49.1118, 45.5559)
  line L13 (44.6118, 48.9559) -> (44.6118, 45.5559)
  arc A1 centre (44.6118, 49.8059) radius 0.85 clockwise from (44.6118, 48.9559) to (44.6118, 50.6559)
extrude "Extrude1" new body sketch "Sketch1" along normal blind 156 (= "width")
position "Position1"
sketch "Sketch1" plane through (0, 0, 0) normal (0, 1, 0) x axis (1, 0, 0)
  line L1 (-2.35, 22.35) -> (-2.35, 31.65)
  line L2 (2.35, 31.65) -> (2.35, 22.35)
  line L3 (0, 20) -> (0, 34)
  arc A1 centre (0, 22.35) radius 2.35 clockwise from (2.35, 22.35) to (-2.35, 22.35)
  arc A2 centre (0, 28.85) radius 2.35 clockwise from (2.35, 28.85) to (-2.35, 28.85)
  arc A3 centre (0, 31.65) radius 2.35 clockwise from (-2.35, 31.65) to (2.35, 31.65)
  point P7 (0, 34)
  point P3 (0, 20)
  point P2 (-2.35, 28.85)
  point P10 (2.35, 28.85)
  point P4 (0, 28.85)
  point P6 (0, 31.65)
  point P13 (0, 0)
  point P14 (0, 0)
  tangent L1 A1
  tangent A1 L2
  parallel L1 L2
  tangent A3 L2
  tangent L1 A3
  midpoint P7 A3
  midpoint P3 A1
  vertical L3
  coincident P2 L1
  coincident P10 L2
  coincident P4 L3
  equal A2 A3
  horizontal P2 P10
  vertical P6 P13
  dimension "d333_1" distance P3 P7 = 14 (= "PegH_3")
  dimension "d334_1" distance L1 L2 = 4.7 (= "PegW_3")
  dimension "d336_1" = 7.5 (= "SkadisSlotH_3 / 2")
  dimension "d341_1" distance A1 P14 = 20
extrude "Extrude1" new body sketch "Sketch1" profile of L1 A2 A3 L2 against normal blind 5.2 named "d342_1" (magnitude of "-PegD_3")
extrude "Extrude2" sketch "Sketch1" profile of L1 A1 A2 A3 L2 blind -5.2 (= "-PegD_3") named "d345_1"
sketch "Sketch3" plane through (0, 39.6118, 0) normal (0, -1, 0) x axis (1, 0, 0)
  line L1 (204, -40) -> (204, 60)
  line L2 (306, -40) -> (204, -40)
  line L3 (306, 60) -> (306, -40)
  line L4 (204, 60) -> (306, 60)
  line L5 (306, 50.6559) -> (204, 50.6559)
  line L6 (255, -40) -> (255, 60)
  circle C1 centre (255, 50.6559) radius 6.3441
  point P8 (255, 60)
  point P9 (255, -40)
  point P10 (255, 50.6559)
  midpoint L4 P8
  midpoint L2 P9
  midpoint L5 P10
position "Position2"
move "Move1"
rectangular_pattern "R-Pattern2" countU 4 (= "ceil(width / 40 / mm)") uSpaceDistance 40 vSpaceDistance 0
sketch "Text" plane through (0, 39.6118, 0) normal (0, -1, 0) x axis (1, 0, 0)
  dimension "d309" = 3
extrude "Extrude2" cut sketch "Text" against normal blind 2
sketch "Filename" plane through (0, 0, 0) normal (0, 1, 0) x axis (1, 0, 0)
  dimension "d312" = 3
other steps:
create_component "CreateComponent1"
create_component "CreateComponent2"
create_component "CreateComponent3"
create_component "CreateComponent5"
create_component "CreateComponent6"
create_component "CreateComponent3"
named bodies: "Wall anchor part", "Base plate with slot", "Screw plate", "Screw hole", "Screw hole (3)", "Screw hole (12)", "Screw plate (2)", "Screw hole (1)", "Screw hole (2)", "Screw hole (4)", "Screw plate (1)", "Screw plate (3)", "Wall anchor part (1)", "Wall anchor part (2)", "Screw hole (5)", "Screw hole (6)", "Screw hole (7)", "Screw hole (8)", "Screw hole (9)", "Screw hole (10)", "Screw hole (11)", "Screw hole (13)", "Screw hole (14)", "Screw plate (4)", "Screw plate (5)"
